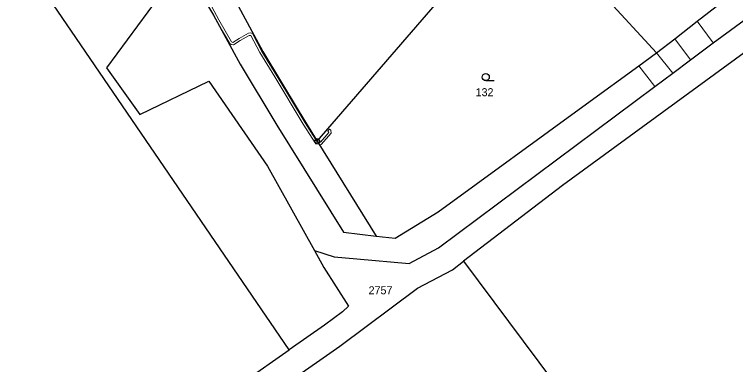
# Model space of a CAD drawing. Extents: x -606517 to -602431, y -1183120 to -1179397.
# Drawn here: x -605631 to -605477.8, y -1181219.7 to -1181145.3 of the extents above; entities that cross this region are included whole.
import ezdxf
from ezdxf.enums import TextEntityAlignment as Align

# ---------------------------------------------------------------- set-up
doc = ezdxf.new("R2010")
doc.units = 0
doc.header["$LTSCALE"] = 0.68
for name, color, linetype, lineweight in [('1', 7, 'Continuous', 25), ('13', 7, 'Continuous', 13), ('3', 7, 'Continuous', 25), ('4', 7, 'Continuous', 13), ('8', 7, 'Continuous', 25)]:
    doc.layers.add(name, color=color, linetype=linetype, lineweight=lineweight)
doc.layers.add('2', color=7, linetype='Continuous')

msp = doc.modelspace()

# ---------------------------------------------------------------- linework, layer by layer
at = {"layer": '1'}
for p, q in [((-605572.61, -1181216.57), (-605656.78, -1181093.27)), ((-605599.71, -1181127.02), (-605588.69, -1181145.43)), ((-605511.29, -1181135.26), (-605494.6, -1181153.48)), ((-605566.67, -1181172.2), (-605536.65, -1181137.41)), ((-605482.61, -1181151.33), (-605465.74, -1181139.01)), ((-605486, -1181146.75), (-605479.29, -1181141.5)), ((-605600.45, -1181141.66), (-605611.43, -1181156.66)), ((-605583.91, -1181142.7), (-605578.24, -1181153.14)), ((-605462.39, -1181143.37), (-605484.12, -1181159.38)), ((-605588.69, -1181145.43), (-605583.02, -1181155.87)), ((-605490.75, -1181150.47), (-605486, -1181146.75)), ((-605494.6, -1181153.48), (-605490.75, -1181150.47)), ((-605487.41, -1181154.97), (-605482.61, -1181151.33)), ((-605578.24, -1181153.14), (-605570.53, -1181165.99)), ((-605498.38, -1181156.24), (-605494.6, -1181153.48)), ((-605491.19, -1181157.79), (-605487.41, -1181154.97)), ((-605611.43, -1181156.66), (-605604.32, -1181166.55)), ((-605583.02, -1181155.87), (-605575.23, -1181168.86)), ((-605509.46, -1181164.33), (-605498.38, -1181156.24)), ((-605494.96, -1181160.6), (-605491.19, -1181157.79)), ((-605604.32, -1181166.55), (-605589.66, -1181159.47)), ((-605589.66, -1181159.47), (-605577.27, -1181177.54)), ((-605484.12, -1181159.38), (-605514.57, -1181181.68)), ((-605540.95, -1181194.9), (-605494.96, -1181160.6)), ((-605541, -1181187.22), (-605509.46, -1181164.33)), ((-605570.53, -1181165.99), (-605566.67, -1181172.2)), ((-605575.23, -1181168.86), (-605561.08, -1181191.61)), ((-605566.67, -1181172.2), (-605554.13, -1181192.4)), ((-605577.27, -1181177.54), (-605567.25, -1181195.51)), ((-605514.57, -1181181.68), (-605535.63, -1181197.76)), ((-605550.11, -1181192.85), (-605541, -1181187.22)), ((-605561.08, -1181191.61), (-605554.13, -1181192.4)), ((-605554.13, -1181192.4), (-605550.11, -1181192.85)), ((-605547.12, -1181198.24), (-605540.95, -1181194.9)), ((-605567.25, -1181195.51), (-605565.3, -1181199.09)), ((-605567.25, -1181195.51), (-605563.08, -1181196.84)), ((-605563.08, -1181196.84), (-605558.27, -1181197.28)), ((-605558.27, -1181197.28), (-605547.12, -1181198.24)), ((-605537.98, -1181199.56), (-605535.63, -1181197.76)), ((-605535.63, -1181197.76), (-605419, -1181354.08)), ((-605565.3, -1181199.09), (-605560, -1181207.31)), ((-605545.38, -1181203.51), (-605537.98, -1181199.56)), ((-605561.89, -1181215.8), (-605545.38, -1181203.51)), ((-605560, -1181207.31), (-605561.28, -1181208.49)), ((-605561.28, -1181208.49), (-605565.16, -1181211.37)), ((-605565.16, -1181211.37), (-605572.61, -1181216.57)), ((-605598.71, -1181234.76), (-605572.61, -1181216.57)), ((-605580.88, -1181229.03), (-605561.89, -1181215.8))]:
    msp.add_line(p, q, dxfattribs=at)
at = {"layer": '13'}
msp.add_lwpolyline([(-605590.53, -1181141.93), (-605588.69, -1181145.43), (-605587.69, -1181147.27), (-605585.23, -1181151.45), (-605584.93, -1181151.71), (-605584.48, -1181151.76), (-605583.01, -1181150.82), (-605581.12, -1181149.75), (-605580.75, -1181149.78), (-605578.87, -1181153.41), (-605575.7, -1181158.57), (-605569.64, -1181168.61), (-605566.98, -1181172.82), (-605566.24, -1181172.89), (-605566.57, -1181172.35), (-605566.68, -1181172.34), (-605569.22, -1181168.35), (-605575.28, -1181158.31), (-605578.43, -1181153.17), (-605580.41, -1181149.36), (-605580.85, -1181149.23), (-605581.28, -1181149.27), (-605583.27, -1181150.4), (-605584.6, -1181151.24), (-605584.85, -1181151.13), (-605587.58, -1181146.47), (-605590.13, -1181141.61)], dxfattribs=at)
msp.add_lwpolyline([(-605564.39, -1181170.05), (-605564.24, -1181170.4), (-605566.01, -1181172.41), (-605566.57, -1181172.35), (-605566.24, -1181172.89), (-605565.81, -1181172.93), (-605563.7, -1181170.56), (-605563.81, -1181169.9), (-605564.06, -1181169.68)], close=True, dxfattribs=at)
at = {"layer": '3'}
msp.add_line((-605530.883, -1181159.36), (-605529.133, -1181159.36), dxfattribs=at)
msp.add_circle((-605530.8829, -1181158.6098), 0.75, dxfattribs=at)
at = {"layer": '4'}
for p, q in [((-605486, -1181146.75), (-605482.61, -1181151.33)), ((-605490.75, -1181150.47), (-605487.41, -1181154.97)), ((-605491.19, -1181157.79), (-605494.6, -1181153.48)), ((-605498.38, -1181156.24), (-605494.96, -1181160.6))]:
    msp.add_line(p, q, dxfattribs=at)
at = {"layer": '8'}
for radius in [0.5, 0.0303]:
    msp.add_circle((-605566.67, -1181172.1999), radius, dxfattribs=at)

# ---------------------------------------------------------------- texts
at = {"layer": '2'}
msp.add_text('132', height=1.7, dxfattribs=at).set_placement((-605531.139, -1181162.675), align=Align.CENTER)
msp.add_text('2757', height=1.7, dxfattribs=at).set_placement((-605555.77, -1181204.785))

doc.saveas('drawing.dxf')
